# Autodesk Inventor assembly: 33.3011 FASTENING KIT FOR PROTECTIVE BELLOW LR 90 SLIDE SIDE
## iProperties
Created: 2007-06
Part Number: 33.3011 FASTENING KIT FOR PROTECTIVE BELLOW LR 90 SLIDE SIDE
Document SubType Name: Assembly
Designer: Andy Moles
Author: Andy Moles
